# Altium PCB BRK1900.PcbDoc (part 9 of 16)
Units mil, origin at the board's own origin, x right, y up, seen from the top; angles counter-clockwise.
Board outline 8858.27 x 5905.51 mil, 10 copper layers (L1-TOP, L2-GND, L3-PWR, L4-GND, L5-PWR, L6-PWR, L7-GND, L8-SIG, L9-GND, L10-BOT), stack 48.824 mil thick; 456 components, 571 nets, 2296 pads, 2416 vias.
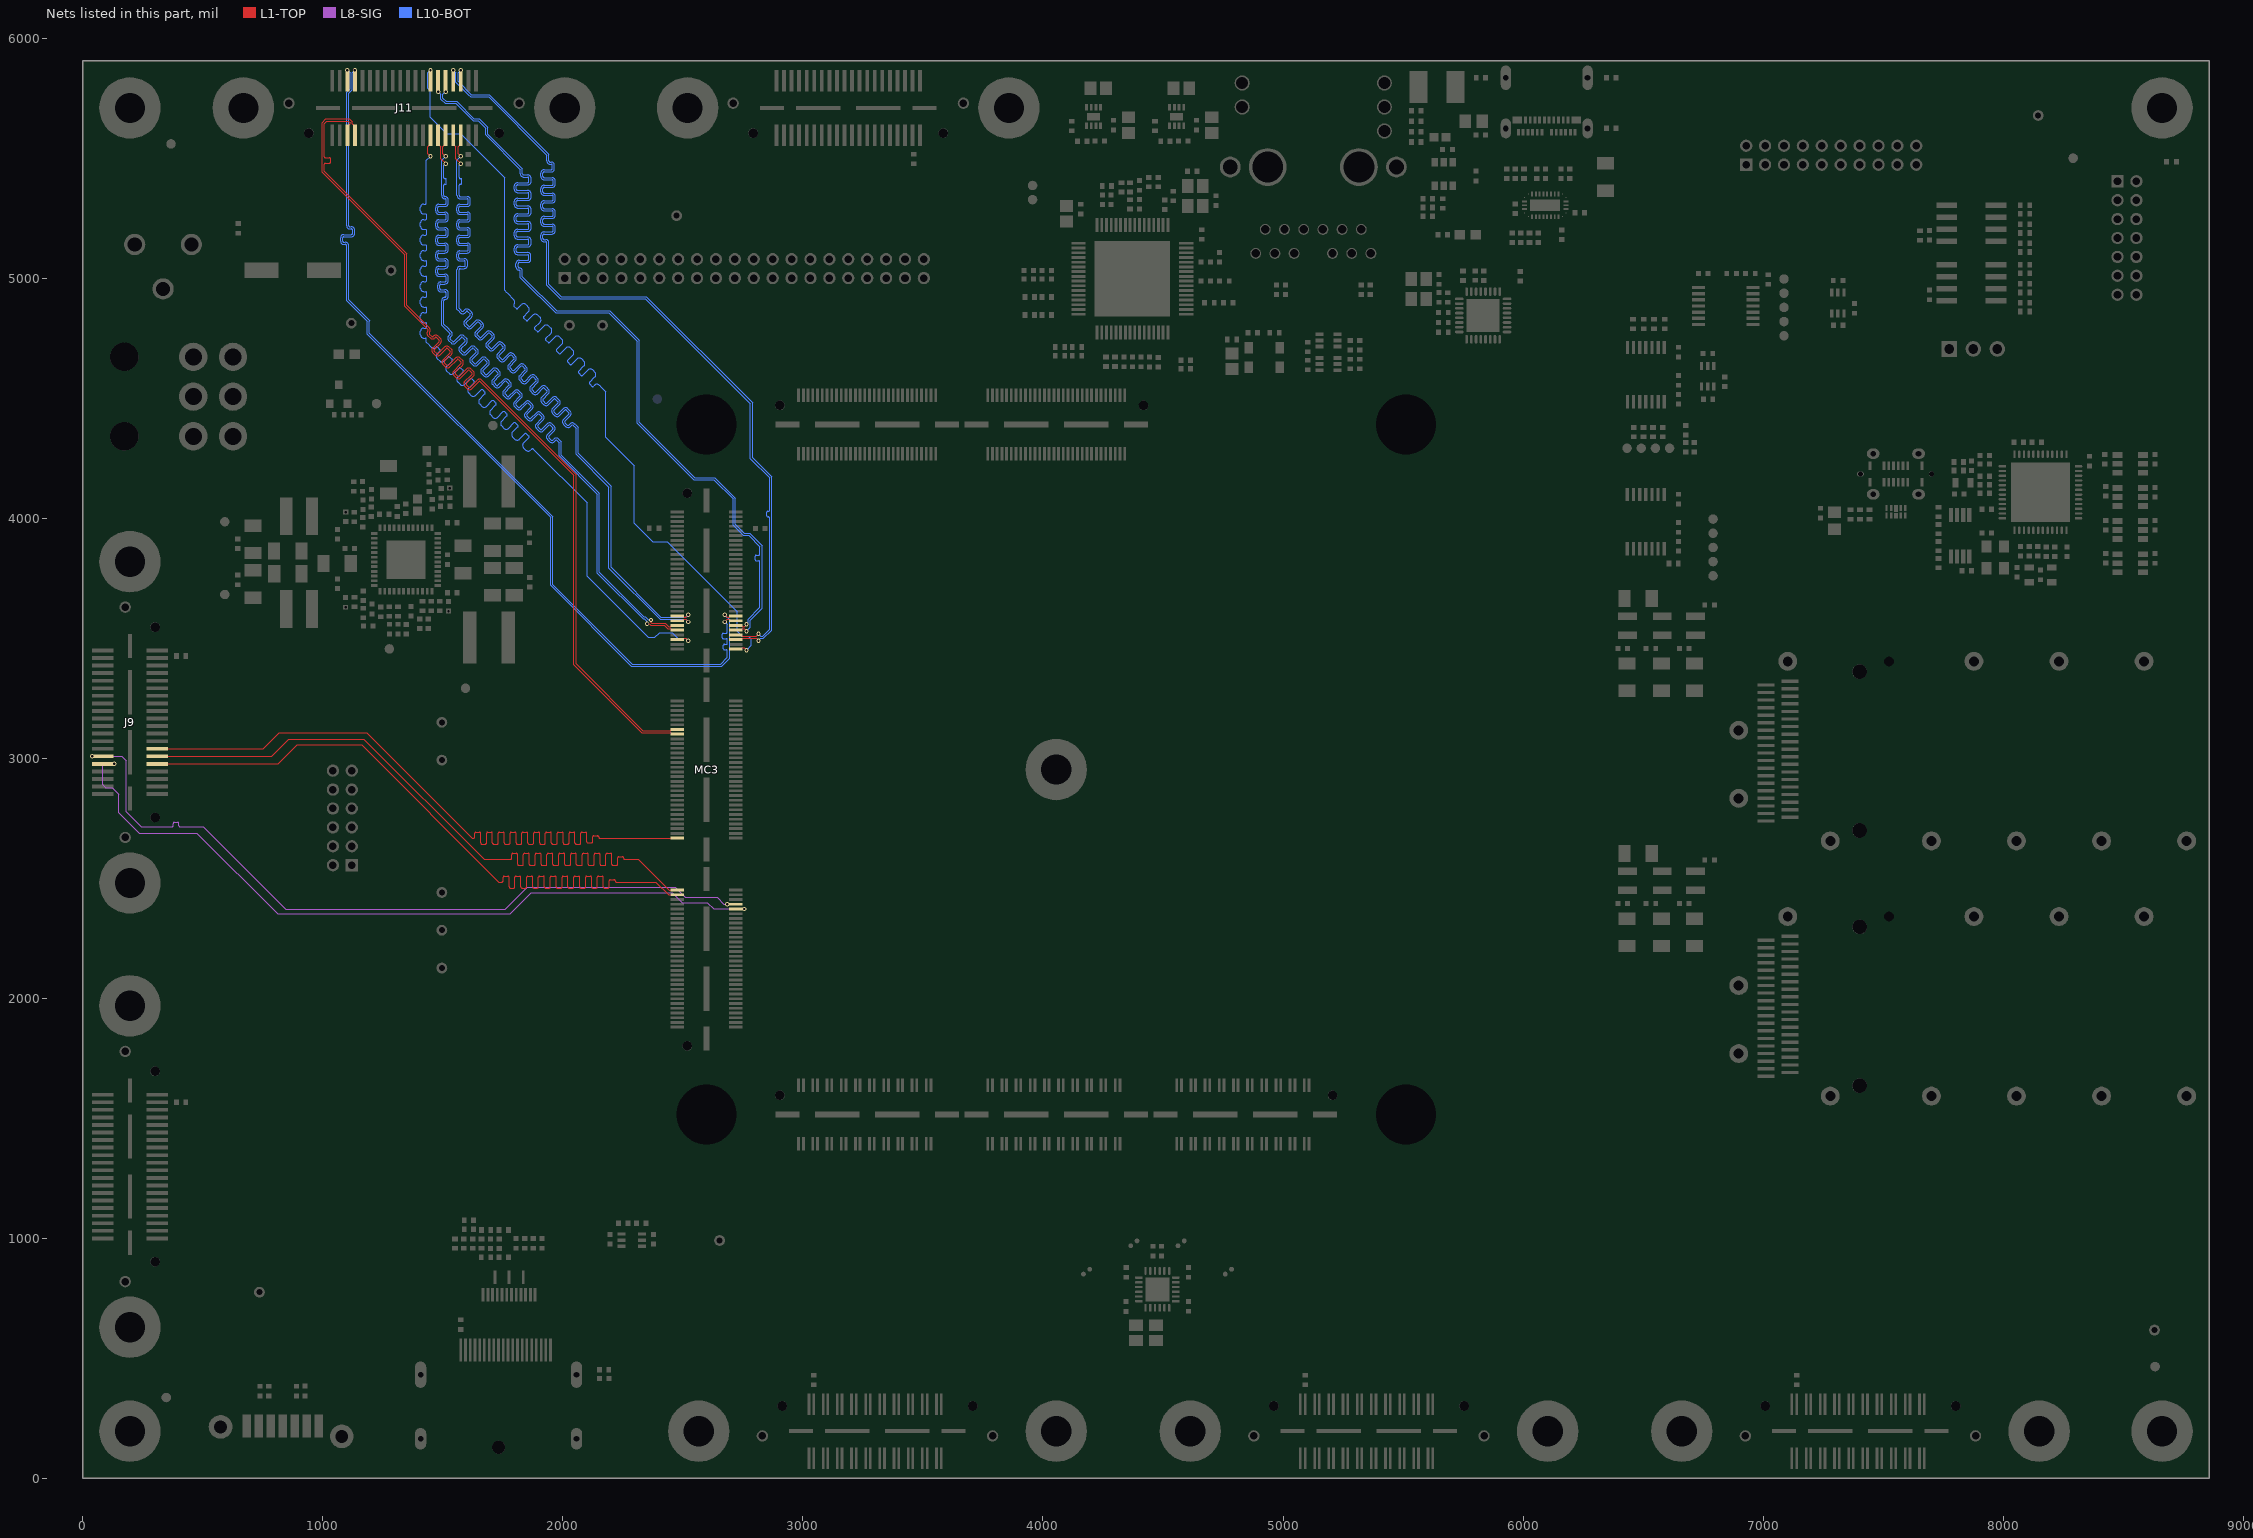
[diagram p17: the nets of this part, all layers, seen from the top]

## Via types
v1: diameter 18, hole 10, L1-TOP to L10-BOT, tented both sides, 2170 vias
v2: diameter 20, hole 10, L1-TOP to L10-BOT, tented both sides, 246 vias

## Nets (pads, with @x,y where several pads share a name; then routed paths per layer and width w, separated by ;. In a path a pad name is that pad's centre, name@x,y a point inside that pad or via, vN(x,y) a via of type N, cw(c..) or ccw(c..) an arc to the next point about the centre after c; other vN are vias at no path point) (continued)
SZG_PORTB_S23: J9.28 MC3.61 | length 3294.4
  L1-TOP w4.55: J9.28@309.65,3039.41 752,3039.41 819.39,3106.79 1182.82,3106.79 1622.28,2667.32 1625.98,2667.32 1628.26,2667.32 ccw(c1628.26,2672.23) 1633.17,2672.23 1633.17,2687.41 cw(c1638.08,2687.41) 1638.08,2692.32 1652.81,2692.32 cw(c1652.81,2687.41) 1657.72,2687.41 1657.72,2647.23 ccw(c1662.63,2647.23) 1662.63,2642.32 1677.36,2642.32 ccw(c1677.36,2647.23) 1682.27,2647.23 1682.27,2687.41 cw(c1687.18,2687.41) 1687.18,2692.32 1701.91,2692.32 cw(c1701.91,2687.41) 1706.82,2687.41 1706.82,2647.23 ccw(c1711.73,2647.23) 1711.73,2642.32 1726.46,2642.32 ccw(c1726.46,2647.23) 1731.37,2647.23 1731.37,2687.41 cw(c1736.28,2687.41) 1736.28,2692.32 1751.01,2692.32 cw(c1751.01,2687.41) 1755.92,2687.41 1755.92,2647.23 ccw(c1760.83,2647.23) 1760.83,2642.32 1775.56,2642.32 ccw(c1775.56,2647.23) 1780.47,2647.23 1780.47,2687.41 cw(c1785.38,2687.41) 1785.38,2692.32 1800.11,2692.32 cw(c1800.11,2687.41) 1805.02,2687.41 1805.02,2647.23 ccw(c1809.93,2647.23) 1809.93,2642.32 1824.66,2642.32 ccw(c1824.66,2647.23) 1829.57,2647.23 1829.57,2687.41 cw(c1834.48,2687.41) 1834.48,2692.32 1849.21,2692.32 cw(c1849.21,2687.41) 1854.12,2687.41 1854.12,2647.23 ccw(c1859.03,2647.23) 1859.03,2642.32 1873.76,2642.32 ccw(c1873.76,2647.23) 1878.67,2647.23 1878.67,2687.41 cw(c1883.58,2687.41) 1883.58,2692.32 1898.31,2692.32 cw(c1898.31,2687.41) 1903.22,2687.41 1903.22,2647.23 ccw(c1908.13,2647.23) 1908.13,2642.32 1922.86,2642.32 ccw(c1922.86,2647.23) 1927.77,2647.23 1927.77,2687.41 cw(c1932.68,2687.41) 1932.68,2692.32 1947.41,2692.32 cw(c1947.41,2687.41) 1952.32,2687.41 1952.32,2647.23 ccw(c1957.23,2647.23) 1957.23,2642.32 1971.96,2642.32 ccw(c1971.96,2647.23) 1976.87,2647.23 1976.87,2687.41 cw(c1981.78,2687.41) 1981.78,2692.32 1996.51,2692.32 cw(c1996.51,2687.41) 2001.42,2687.41 2001.42,2647.23 ccw(c2006.33,2647.23) 2006.33,2642.32 2021.06,2642.32 ccw(c2021.06,2647.23) 2025.97,2647.23 2025.97,2687.41 cw(c2030.88,2687.41) 2030.88,2692.32 2045.61,2692.32 cw(c2045.61,2687.41) 2050.52,2687.41 2050.52,2647.23 ccw(c2055.43,2647.23) 2055.43,2642.32 2070.16,2642.32 ccw(c2070.16,2647.23) 2075.07,2647.23 2075.07,2687.41 cw(c2079.98,2687.41) 2079.98,2692.32 2094.71,2692.32 cw(c2094.71,2687.41) 2099.62,2687.41 2099.62,2652.02 ccw(c2104.53,2652.02) 2104.53,2647.11 2119.26,2647.11 ccw(c2119.26,2652.02) 2124.17,2652.02 2124.17,2672.23 cw(c2129.08,2672.23) 2129.08,2677.14 2143.81,2677.14 cw(c2143.81,2672.23) 2148.72,2672.23 ccw(c2153.63,2672.23) 2153.63,2667.32 2228.35,2667.32 MC3.61@2476.77,2667.32
SZG_PORTB_S24: J9.29 MC3.54 | length 3133.3
  L8-SIG w4.05: v1@36.05,3007.91 162.86,3007.91 181.76,2989.01 181.76,2776.24 244,2714 370.08,2714 372.1,2714 ccw(c372.1,2718.81) 376.91,2718.81 376.91,2727.72 cw(c381.72,2727.72) 381.72,2732.54 396.15,2732.54 cw(c396.15,2727.72) 400.96,2727.72 400.96,2718.81 ccw(c405.77,2718.81) 405.77,2714 433.07,2714 503,2714 846.24,2370.76 1760.53,2370.76 1851.76,2462 2468,2462 2510,2420 2642.99,2420 2671.26,2391.73 v1(2685.08,2391.73)
  other v1: 39.35,3007.91
SZG_PORTB_S25: J9.30 MC3.59 | length 3294.4
  L1-TOP w4.55: J9.30@309.65,3007.91 787.43,3007.91 858.76,3079.23 1171.4,3079.23 1671.89,2578.74 1779.53,2578.74 1781.8,2578.74 ccw(c1781.8,2583.65) 1786.71,2583.65 1786.71,2598.83 cw(c1791.62,2598.83) 1791.62,2603.74 1806.35,2603.74 cw(c1806.35,2598.83) 1811.26,2598.83 1811.26,2558.65 ccw(c1816.17,2558.65) 1816.17,2553.74 1830.9,2553.74 ccw(c1830.9,2558.65) 1835.81,2558.65 1835.81,2598.83 cw(c1840.72,2598.83) 1840.72,2603.74 1855.45,2603.74 cw(c1855.45,2598.83) 1860.36,2598.83 1860.36,2558.65 ccw(c1865.27,2558.65) 1865.27,2553.74 1880,2553.74 ccw(c1880,2558.65) 1884.91,2558.65 1884.91,2598.83 cw(c1889.82,2598.83) 1889.82,2603.74 1904.55,2603.74 cw(c1904.55,2598.83) 1909.46,2598.83 1909.46,2558.65 ccw(c1914.37,2558.65) 1914.37,2553.74 1929.1,2553.74 ccw(c1929.1,2558.65) 1934.01,2558.65 1934.01,2598.83 cw(c1938.92,2598.83) 1938.92,2603.74 1953.65,2603.74 cw(c1953.65,2598.83) 1958.56,2598.83 1958.56,2558.65 ccw(c1963.47,2558.65) 1963.47,2553.74 1978.2,2553.74 ccw(c1978.2,2558.65) 1983.11,2558.65 1983.11,2598.83 cw(c1988.02,2598.83) 1988.02,2603.74 2002.75,2603.74 cw(c2002.75,2598.83) 2007.66,2598.83 2007.66,2558.65 ccw(c2012.57,2558.65) 2012.57,2553.74 2027.3,2553.74 ccw(c2027.3,2558.65) 2032.21,2558.65 2032.21,2598.83 cw(c2037.12,2598.83) 2037.12,2603.74 2051.85,2603.74 cw(c2051.85,2598.83) 2056.76,2598.83 2056.76,2558.65 ccw(c2061.67,2558.65) 2061.67,2553.74 2076.4,2553.74 ccw(c2076.4,2558.65) 2081.31,2558.65 2081.31,2598.83 cw(c2086.22,2598.83) 2086.22,2603.74 2100.95,2603.74 cw(c2100.95,2598.83) 2105.86,2598.83 2105.86,2558.65 ccw(c2110.77,2558.65) 2110.77,2553.74 2125.5,2553.74 ccw(c2125.5,2558.65) 2130.41,2558.65 2130.41,2598.83 cw(c2135.32,2598.83) 2135.32,2603.74 2150.05,2603.74 cw(c2150.05,2598.83) 2154.96,2598.83 2154.96,2558.65 ccw(c2159.87,2558.65) 2159.87,2553.74 2174.6,2553.74 ccw(c2174.6,2558.65) 2179.51,2558.65 2179.51,2598.83 cw(c2184.42,2598.83) 2184.42,2603.74 2199.15,2603.74 cw(c2199.15,2598.83) 2204.06,2598.83 2204.06,2558.65 ccw(c2208.97,2558.65) 2208.97,2553.74 2223.7,2553.74 ccw(c2223.7,2558.65) 2228.61,2558.65 2228.61,2584.69 cw(c2233.52,2584.69) 2233.52,2589.6 2248.25,2589.6 cw(c2248.25,2584.69) 2253.16,2584.69 2253.16,2583.65 ccw(c2258.07,2583.65) 2258.07,2578.74 2303.15,2578.74 2314.96,2578.74 2442.91,2450.79 MC3.59@2476.77,2450.79
SZG_PORTB_S26: J9.31 MC3.52 | length 3133.3
  L8-SIG w4.05: v1(132.05,2976.41) 92.16,2976.41 84.37,2968.62 84.37,2889.91 96.33,2877.95 122.05,2877.95 149.55,2850.45 149.55,2773.02 234.56,2688 476,2688 812.24,2351.76 1780.9,2351.76 1869.13,2440 2456,2440 2498,2398 2602,2398 2627.95,2372.05 v1(2755.08,2372.05)
SZG_PORTB_S27: J9.32 MC3.57 | length 3294.4
  L1-TOP w4.55: J9.32@309.65,2976.41 814.99,2976.41 893.7,3055.12 1161.42,3055.12 1732.28,2484.25 1744.09,2484.25 1746.37,2484.25 ccw(c1746.37,2489.16) 1751.28,2489.16 1751.28,2504.34 cw(c1756.19,2504.34) 1756.19,2509.25 1770.92,2509.25 cw(c1770.92,2504.34) 1775.83,2504.34 1775.83,2464.16 ccw(c1780.74,2464.16) 1780.74,2459.25 1795.47,2459.25 ccw(c1795.47,2464.16) 1800.38,2464.16 1800.38,2504.34 cw(c1805.29,2504.34) 1805.29,2509.25 1820.02,2509.25 cw(c1820.02,2504.34) 1824.93,2504.34 1824.93,2464.16 ccw(c1829.84,2464.16) 1829.84,2459.25 1844.57,2459.25 ccw(c1844.57,2464.16) 1849.48,2464.16 1849.48,2504.34 cw(c1854.39,2504.34) 1854.39,2509.25 1869.12,2509.25 cw(c1869.12,2504.34) 1874.03,2504.34 1874.03,2464.16 ccw(c1878.94,2464.16) 1878.94,2459.25 1893.67,2459.25 ccw(c1893.67,2464.16) 1898.58,2464.16 1898.58,2504.34 cw(c1903.49,2504.34) 1903.49,2509.25 1918.22,2509.25 cw(c1918.22,2504.34) 1923.13,2504.34 1923.13,2464.16 ccw(c1928.04,2464.16) 1928.04,2459.25 1942.77,2459.25 ccw(c1942.77,2464.16) 1947.68,2464.16 1947.68,2504.34 cw(c1952.59,2504.34) 1952.59,2509.25 1967.32,2509.25 cw(c1967.32,2504.34) 1972.23,2504.34 1972.23,2464.16 ccw(c1977.14,2464.16) 1977.14,2459.25 1991.87,2459.25 ccw(c1991.87,2464.16) 1996.78,2464.16 1996.78,2504.34 cw(c2001.69,2504.34) 2001.69,2509.25 2016.42,2509.25 cw(c2016.42,2504.34) 2021.33,2504.34 2021.33,2464.16 ccw(c2026.24,2464.16) 2026.24,2459.25 2040.97,2459.25 ccw(c2040.97,2464.16) 2045.88,2464.16 2045.88,2504.34 cw(c2050.79,2504.34) 2050.79,2509.25 2065.52,2509.25 cw(c2065.52,2504.34) 2070.43,2504.34 2070.43,2464.16 ccw(c2075.34,2464.16) 2075.34,2459.25 2090.07,2459.25 ccw(c2090.07,2464.16) 2094.98,2464.16 2094.98,2504.34 cw(c2099.89,2504.34) 2099.89,2509.25 2114.62,2509.25 cw(c2114.62,2504.34) 2119.53,2504.34 2119.53,2464.16 ccw(c2124.44,2464.16) 2124.44,2459.25 2139.17,2459.25 ccw(c2139.17,2464.16) 2144.08,2464.16 2144.08,2504.34 cw(c2148.99,2504.34) 2148.99,2509.25 2163.72,2509.25 cw(c2163.72,2504.34) 2168.63,2504.34 2168.63,2464.16 ccw(c2173.54,2464.16) 2173.54,2459.25 2188.27,2459.25 ccw(c2188.27,2464.16) 2193.18,2464.16 2193.18,2489.59 cw(c2198.09,2489.59) 2198.09,2494.5 2212.82,2494.5 cw(c2212.82,2489.59) 2217.73,2489.59 2217.73,2489.16 ccw(c2222.64,2489.16) 2222.64,2484.25 2299.21,2484.25 2387.75,2484.25 2440.9,2431.1 MC3.57@2476.77,2431.1
SZG_PORTC_C2P_CLKN: J11.36 MC3.107 | length 3871
  L1-TOP w3.3: J11.36@1102.38,5595.86 1102.38,5632.38 1113.63,5643.63 1113.63,5646.73 1106.51,5653.85 1016.85,5653.85 1006,5643 1006,5554.73 1006,5506.35 ccw(c1010.66,5506.35) 1010.66,5501.69 1027.71,5501.69 cw(c1027.71,5497.03) 1032.37,5497.03 1032.37,5483.05 cw(c1027.71,5483.05) 1027.71,5478.39 1010.66,5478.39 ccw(c1010.66,5473.73) 1006,5473.73 1006,5448.78 1006,5444.73 1350,5100.73 1350,4886.81 1417.81,4819.01 1420.84,4815.98 1443.98,4792.83 cw(c1434.33,4783.17) 1443.98,4773.51 ccw(c1447.28,4770.22) 1443.98,4766.92 1453.87,4757.04 ccw(c1457.16,4760.33) 1460.46,4757.04 1462.84,4759.41 1463.05,4759.41 cw(c1471.18,4748.44) 1480.84,4758.09 1490.72,4748.21 cw(c1481.06,4738.55) 1490.7,4728.87 1464.22,4702.39 ccw(c1467.51,4699.09) 1464.22,4695.8 1474.1,4685.91 ccw(c1477.4,4689.2) 1480.69,4685.91 1508.52,4713.73 1508.73,4713.73 cw(c1516.86,4702.76) 1526.52,4712.42 1536.4,4702.53 cw(c1526.74,4692.87) 1536.43,4683.25 1506.72,4653.53 ; 1506.7,4653.51 ccw(c1509.99,4650.21) 1506.7,4646.92 1516.58,4637.03 ccw(c1519.88,4640.33) 1523.17,4637.03 1554.19,4668.05 1554.41,4668.05 cw(c1562.54,4657.08) 1572.19,4666.74 1582.08,4656.85 cw(c1572.42,4647.19) 1582.11,4637.57 1552.4,4607.85 ; 1552.38,4607.83 ccw(c1555.67,4604.53) 1552.38,4601.24 1562.26,4591.35 ccw(c1565.56,4594.65) 1568.85,4591.35 1599.87,4622.38 1600.08,4622.38 cw(c1608.21,4611.4) 1617.87,4621.06 1627.76,4611.17 cw(c1618.1,4601.51) 1627.79,4591.89 1598.08,4562.17 ; 1598.05,4562.15 ccw(c1601.35,4558.86) 1598.05,4555.56 1607.94,4545.67 ccw(c1611.24,4548.97) 1614.53,4545.68 1643.18,4574.32 cw(c1652.83,4564.66) 1660.96,4575.64 1661.18,4575.64 1662.48,4574.33 1663.81,4573 1666.84,4569.97 2055,4181.81 2055,3393 2333.26,3114.74 2448.6,3114.74 2453.95,3120.08 MC3.107@2476.77,3120.08
SZG_PORTC_C2P_CLKP: J11.34 MC3.105 | length 3870.8
  L1-TOP w3.3: J11.34@1133.88,5595.86 1133.88,5632.65 1122.63,5643.9 1122.63,5650.45 1110.24,5662.85 1013.12,5662.85 997,5646.73 997,5441 1341,5097 1341,4883.09 1411.44,4812.64 1414.47,4809.61 1437.62,4786.47 cw(c1434.33,4783.17) 1437.62,4779.88 ccw(c1447.28,4770.22) 1437.65,4760.53 1447.48,4750.7 ; 1447.48,4750.7 ccw(c1457.16,4760.33) 1466.82,4750.67 1467.86,4751.71 ; 1467.88,4751.73 cw(c1471.18,4748.44) 1474.47,4751.73 1484.36,4741.85 cw(c1481.06,4738.55) 1484.36,4735.26 1457.85,4708.75 ccw(c1467.51,4699.09) 1457.88,4689.41 1467.71,4679.57 ccw(c1477.4,4689.2) 1487.06,4679.55 1513.54,4706.03 cw(c1516.86,4702.76) 1520.15,4706.05 1530.04,4696.17 cw(c1526.74,4692.87) 1530.04,4689.58 1499.01,4658.55 1499.01,4658.34 ccw(c1509.99,4650.21) 1500.36,4640.53 1510.19,4630.7 ccw(c1519.88,4640.33) 1529.54,4630.67 1559.22,4660.35 ; 1555.87,4585.02 ccw(c1565.56,4594.65) 1575.22,4584.99 1604.9,4614.67 cw(c1608.21,4611.4) 1611.51,4614.69 1621.39,4604.81 cw(c1618.1,4601.51) 1621.39,4598.22 1590.37,4567.2 1590.37,4566.99 ccw(c1601.35,4558.86) 1591.72,4549.17 1601.55,4539.34 ccw(c1611.24,4548.97) 1620.89,4539.31 1649.54,4567.96 cw(c1652.83,4564.66) 1656.15,4567.94 1657.45,4566.64 1660.48,4563.61 2046,4178.09 2046,3389.27 2329.54,3105.74 2448.92,3105.74 2454.26,3100.39 MC3.105@2476.77,3100.39 ; 1555.87,4585.02 1546.04,4594.85 cw(c1555.67,4604.53) 1544.69,4612.66 1544.69,4612.88 1575.72,4643.9 ccw(c1572.42,4647.19) 1575.72,4650.49 1565.83,4660.37 ccw(c1562.54,4657.08) 1559.24,4660.37
SZG_PORTC_P2C_CLKN: J11.35 MC3.136 | length 3724
  L1-TOP w3.3: v1@2675.08,3596.46 2676.08,3596.46 2685.36,3587.18 2692.1,3587.18 2697.44,3592.52 MC3.136@2720.08,3592.52
  L10-BOT w3.3: v1@1103.37,5866.17 1113.63,5855.9 1113.63,5789 1099,5774.37 1099,5297.6 1099,5218.49 ccw(c1112.66,5218.49) 1112.66,5204.83 1119.34,5204.83 cw(c1119.34,5200.17) 1124,5200.17 1124,5186.19 cw(c1119.34,5186.19) 1119.34,5181.53 1087.66,5181.53 ccw(c1087.66,5167.87) 1074,5167.87 1074,5153.89 ccw(c1087.66,5153.89) 1087.66,5140.23 1094.34,5140.23 cw(c1094.34,5135.57) 1099,5135.57 1099,5129.42 1099,4906.27 1185,4820.27 1185,4766.84 1948.82,4003.02 1948.82,3719.56 2285.37,3383 2661.73,3383 2694.78,3416.05 2694.78,3576.76 v1@2675.08,3596.46
  other v1: 2675.08,3597.46 1102.37,5866.17
SZG_PORTC_P2C_CLKP: J11.33 MC3.134 | length 3722.9
  L1-TOP w3.3: v1@2675.08,3568.9 2676.18,3568.9 2685.46,3578.18 2692.1,3578.18 2697.44,3572.83 MC3.134@2720.08,3572.83
  L10-BOT w3.3: v1@1132.89,5866.17 1122.63,5855.9 1122.63,5785.27 1108,5770.64 1108,5297.6 1108,5218.49 ccw(c1112.66,5218.49) 1112.66,5213.83 1119.34,5213.83 cw(c1119.34,5200.17) 1133,5200.17 1133,5186.19 cw(c1119.34,5186.19) 1119.34,5172.53 1087.66,5172.53 ccw(c1087.66,5167.87) 1083,5167.87 1083,5153.89 ccw(c1087.66,5153.89) 1087.66,5149.23 1094.34,5149.23 cw(c1094.34,5135.57) 1108,5135.57 1108,5129.42 1108,4910 1195.5,4822.5 ; 1194,4821 1194,4770.57 1957.82,4006.75 1957.82,3723.28 2289.1,3392 2658,3392 2685.78,3419.78 2685.78,3426.42 2685.78,3446.83 ccw(c2681.12,3446.83) 2681.12,3451.49 2673.71,3451.49 cw(c2673.71,3456.15) 2669.05,3456.15 2669.05,3470.13 cw(c2673.71,3470.13) 2673.71,3474.79 2681.12,3474.79 ccw(c2681.12,3479.45) 2685.78,3479.45 2685.78,3493.43 ccw(c2681.12,3493.43) 2681.12,3498.09 2668.76,3498.09 cw(c2668.76,3502.75) 2664.1,3502.75 2664.1,3516.73 cw(c2668.76,3516.73) 2668.76,3521.39 2681.12,3521.39 ccw(c2681.12,3526.05) 2685.78,3526.05 2685.78,3551 2685.78,3558.2 v1@2675.08,3568.9
  other v1: 2675.08,3567.8 1133.89,5866.17
SZG_PORTC_S0_D0P: J11.5 MC3.126 | length 3724.1
  L1-TOP w3.3: MC3.126@2720.08,3494.09 2742.67,3494.09 2748.01,3499.44 2805.8,3499.44 v1@2815.08,3490.16
  L10-BOT w3.3: v1@1573.89,5866.17 1563.63,5855.9 1563.63,5819.37 1619.11,5763.89 1694.11,5763.89 1939.43,5518.57 1942.07,5515.93 1942.07,5504.67 1942.07,5487.97 ccw(c1946.73,5487.97) 1946.73,5483.31 1951.3,5483.31 cw(c1951.3,5469.65) 1964.96,5469.65 1964.96,5455.67 cw(c1951.3,5455.67) 1951.3,5442.01 1921.73,5442.01 ccw(c1921.73,5437.35) 1917.07,5437.35 1917.07,5423.37 ccw(c1921.73,5423.37) 1921.73,5418.71 1954.89,5418.71 cw(c1954.89,5405.05) 1968.55,5405.05 1968.55,5391.07 cw(c1954.89,5391.07) 1954.89,5377.41 1921.73,5377.41 ccw(c1921.73,5372.75) 1917.07,5372.75 1917.07,5358.77 ccw(c1921.73,5358.77) 1921.73,5354.11 1954.89,5354.11 cw(c1954.89,5340.45) 1968.55,5340.45 1968.55,5326.47 cw(c1954.89,5326.47) 1954.89,5312.81 1921.73,5312.81 ccw(c1921.73,5308.15) 1917.07,5308.15 1917.07,5294.17 ccw(c1921.73,5294.17) 1921.73,5289.51 1954.89,5289.51 cw(c1954.89,5275.85) 1968.55,5275.85 1968.55,5261.87 cw(c1954.89,5261.87) 1954.89,5248.21 1921.73,5248.21 ccw(c1921.73,5243.55) 1917.07,5243.55 1917.07,5229.57 ccw(c1921.73,5229.57) 1921.73,5224.91 1954.89,5224.91 cw(c1954.89,5211.25) 1968.55,5211.25 1968.55,5197.27 cw(c1954.89,5197.27) 1954.89,5183.61 1921.73,5183.61 ccw(c1921.73,5178.95) 1917.07,5178.95 1917.07,5164.97 ccw(c1921.73,5164.97) 1921.73,5160.31 1928.41,5160.31 cw(c1928.41,5146.65) 1942.07,5146.65 1942.07,5140.5 1942.07,4973.93 1993,4923 2346.73,4923 2790.04,4479.69 2790.04,4251.8 2870,4171.84 2870,4058.09 2870,3533.71 2835.73,3499.44 2824.36,3499.44 v1@2815.08,3490.16
  other v1: 2815.08,3489.06 1574.89,5866.17
SZG_PORTC_S1_D1P: J11.6 MC3.133 | length 3773.8
  L1-TOP w3.3: v1(1574.88,5507.28) 1563.63,5518.53 1563.63,5547.62 1574.88,5558.87 J11.6@1574.88,5595.86 ; MC3.133@2476.77,3572.83 2499.41,3572.83 2504.7,3578.13 2512.7,3578.13 2521.77,3569.06 v1@2521.77,3568.9
  L10-BOT w3.3: v1(1574.88,5507.28) 1559,5491.4 1559,5350.39 1559,5344.24 ccw(c1572.66,5344.24) 1572.66,5330.58 1601.49,5330.58 cw(c1601.49,5325.92) 1606.15,5325.92 1606.15,5311.94 cw(c1601.49,5311.94) 1601.49,5307.28 1570.94,5307.28 ccw(c1570.94,5293.62) 1557.28,5293.62 1557.28,5279.64 ccw(c1570.94,5279.64) 1570.94,5265.98 1601.49,5265.98 cw(c1601.49,5261.32) 1606.15,5261.32 1606.15,5247.34 cw(c1601.49,5247.34) 1601.49,5242.68 1570.94,5242.68 ccw(c1570.94,5229.02) 1557.28,5229.02 1557.28,5215.04 ccw(c1570.94,5215.04) 1570.94,5201.38 1601.49,5201.38 cw(c1601.49,5196.72) 1606.15,5196.72 1606.15,5182.74 cw(c1601.49,5182.74) 1601.49,5178.08 1570.94,5178.08 ccw(c1570.94,5164.42) 1557.28,5164.42 1557.28,5150.44 ccw(c1570.94,5150.44) 1570.94,5136.78 1601.49,5136.78 cw(c1601.49,5132.12) 1606.15,5132.12 1606.15,5118.14 cw(c1601.49,5118.14) 1601.49,5113.48 1570.94,5113.48 ccw(c1570.94,5099.82) 1557.28,5099.82 1557.28,5085.84 ccw(c1570.94,5085.84) 1570.94,5072.18 1589.47,5072.18 cw(c1589.47,5067.52) 1594.13,5067.52 1594.13,5053.54 cw(c1589.47,5053.54) 1589.47,5048.88 1572.66,5048.88 ccw(c1572.66,5035.22) 1559,5035.22 1559,4958.09 1559,4870.13 1560.42,4868.72 1563.45,4865.69 1573.15,4855.98 ccw(c1582.81,4865.64) 1592.47,4855.98 1597.17,4860.68 ; 1597.19,4860.71 cw(c1600.49,4857.41) 1603.78,4860.71 1613.67,4850.82 cw(c1610.37,4847.53) 1613.67,4844.23 1589.95,4820.51 1589.95,4820.3 ccw(c1600.93,4812.17) 1591.29,4802.49 1601.12,4792.65 ccw(c1610.81,4802.28) 1620.47,4792.63 1642.85,4815 ; 1642.87,4815.03 cw(c1646.17,4811.73) 1649.46,4815.03 1659.35,4805.14 cw(c1656.05,4801.85) 1659.35,4798.55 1635.63,4774.83 1635.63,4774.62 ccw(c1646.61,4766.49) 1636.97,4756.81 1646.8,4746.98 ccw(c1656.49,4756.61) 1666.15,4746.95 1688.53,4769.33 cw(c1691.85,4766.05) 1695.14,4769.35 1705.03,4759.46 cw(c1701.73,4756.17) 1705.03,4752.87 1681.31,4729.15 1681.31,4728.94 ccw(c1692.28,4720.81) 1682.65,4711.13 1692.48,4701.3 ccw(c1702.17,4710.93) 1711.83,4701.27 1734.21,4723.65 ; 1734.23,4723.67 cw(c1737.53,4720.37) 1740.82,4723.67 1750.71,4713.78 cw(c1747.41,4710.49) 1750.71,4707.19 1726.99,4683.47 1726.99,4683.26 ccw(c1737.96,4675.13) 1728.33,4665.45 1738.16,4655.62 ; 1738.16,4655.62 ccw(c1747.85,4665.25) 1757.51,4655.59 1779.89,4677.97 cw(c1783.2,4674.7) 1786.5,4677.99 1796.38,4668.1 cw(c1793.09,4664.81) 1796.38,4661.51 1772.67,4637.8 1772.67,4637.58 ccw(c1783.64,4629.45) 1774.01,4619.77 ; 1774.01,4619.77 1783.84,4609.94 ccw(c1793.53,4619.57) 1803.19,4609.91 1825.57,4632.29 ; 1825.59,4632.31 cw(c1828.88,4629.02) 1832.18,4632.31 1842.06,4622.43 cw(c1838.77,4619.13) 1842.06,4615.84 1818.34,4592.12 1818.34,4591.91 ccw(c1829.32,4583.78) 1819.69,4574.09 1829.52,4564.26 ccw(c1839.21,4573.89) 1848.87,4564.23 1871.24,4586.61 ; 1871.27,4586.63 cw(c1874.56,4583.34) 1877.86,4586.63 1887.74,4576.75 cw(c1884.45,4573.45) 1887.74,4570.16 1864.02,4546.44 1864.02,4546.23 ccw(c1875,4538.1) 1865.37,4528.41 1875.2,4518.58 ccw(c1884.89,4528.21) 1894.54,4518.55 1916.92,4540.93 ; 1916.95,4540.95 cw(c1920.24,4537.66) 1923.54,4540.95 1933.42,4531.07 cw(c1930.13,4527.77) 1933.42,4524.48 1909.7,4500.76 1909.7,4500.55 ccw(c1920.68,4492.42) 1911.05,4482.73 1920.88,4472.9 ccw(c1930.56,4482.53) 1940.22,4472.87 1962.6,4495.25 ; 1956.73,4437.05 cw(c1966.36,4446.74) 1955.38,4454.87 1955.38,4455.08 1979.1,4478.8 ccw(c1975.81,4482.09) 1979.1,4485.39 1969.21,4495.27 ccw(c1965.92,4491.98) 1962.62,4495.27 ; 1956.73,4437.05 1966.56,4427.22 ccw(c1976.24,4436.85) 1985.9,4427.19 2008.28,4449.57 cw(c2011.6,4446.3) 2014.89,4449.6 2024.78,4439.71 cw(c2021.48,4436.41) 2024.78,4433.12 2001.06,4409.4 2001.06,4409.19 ccw(c2012.04,4401.06) 2002.4,4391.37 2012.23,4381.54 ccw(c2021.92,4391.17) 2031.58,4381.51 2036.31,4386.24 cw(c2039.6,4382.94) 2042.91,4386.22 ; 2042.92,4386.21 2044.21,4384.92 2047.24,4381.89 2055.12,4374.02 2055.12,4266.35 2192,4129.47 2192,3791.16 2404.98,3578.18 2512.49,3578.18 v1@2521.77,3568.9
  other v1: 2521.77,3567.8
SZG_PORTC_S2_D0N: J11.7 MC3.128 | length 3724.3
  L1-TOP w3.3: MC3.128@2720.08,3513.78 2742.76,3513.78 2748.1,3508.44 2805.8,3508.44 v1@2815.08,3517.72
  L10-BOT w3.3: v1@1544.37,5866.17 1554.63,5855.9 1554.63,5815.64 1603.64,5766.64 1615.38,5754.89 1690.38,5754.89 1933.07,5512.2 1933.07,5504.67 1933.07,5487.97 ccw(c1946.73,5487.97) 1946.73,5474.31 1951.3,5474.31 cw(c1951.3,5469.65) 1955.96,5469.65 1955.96,5455.67 cw(c1951.3,5455.67) 1951.3,5451.01 1921.73,5451.01 ccw(c1921.73,5437.35) 1908.07,5437.35 1908.07,5423.37 ccw(c1921.73,5423.37) 1921.73,5409.71 1954.89,5409.71 cw(c1954.89,5405.05) 1959.55,5405.05 1959.55,5391.07 cw(c1954.89,5391.07) 1954.89,5386.41 1921.73,5386.41 ccw(c1921.73,5372.75) 1908.07,5372.75 1908.07,5358.77 ccw(c1921.73,5358.77) 1921.73,5345.11 1954.89,5345.11 cw(c1954.89,5340.45) 1959.55,5340.45 1959.55,5326.47 cw(c1954.89,5326.47) 1954.89,5321.81 1921.73,5321.81 ccw(c1921.73,5308.15) 1908.07,5308.15 1908.07,5294.17 ccw(c1921.73,5294.17) 1921.73,5280.51 1954.89,5280.51 cw(c1954.89,5275.85) 1959.55,5275.85 1959.55,5261.87 cw(c1954.89,5261.87) 1954.89,5257.21 1921.73,5257.21 ccw(c1921.73,5243.55) 1908.07,5243.55 1908.07,5229.57 ccw(c1921.73,5229.57) 1921.73,5215.91 1954.89,5215.91 cw(c1954.89,5211.25) 1959.55,5211.25 1959.55,5197.27 cw(c1954.89,5197.27) 1954.89,5192.61 1921.73,5192.61 ccw(c1921.73,5178.95) 1908.07,5178.95 1908.07,5164.97 ccw(c1921.73,5164.97) 1921.73,5151.31 1928.41,5151.31 cw(c1928.41,5146.65) 1933.07,5146.65 1933.07,5140.5 1933.07,4970.2 1989.27,4914 2343,4914 2781.04,4475.96 2781.04,4248.07 2861,4168.11 2861,4058.09 2861,4033.14 cw(c2856.34,4033.14) 2856.34,4028.48 2854.1,4028.48 ccw(c2854.1,4023.82) 2849.44,4023.82 2849.44,4009.84 ccw(c2854.1,4009.84) 2854.1,4005.18 2856.34,4005.18 cw(c2856.34,4000.52) 2861,4000.52 2861,3984.25 2861,3537.44 2832,3508.44 2824.36,3508.44 v1@2815.08,3517.72
  other v1: 2815.08,3518.72 1543.37,5866.17
SZG_PORTC_S3_D1N: J11.8 MC3.135 | length 3773.8
  L1-TOP w3.3: J11.8@1543.38,5595.86 1543.38,5559 1554.63,5547.75 1554.63,5498 v1@1574.88,5477.75 ; MC3.135@2476.77,3592.52 2499.41,3592.52 2504.8,3587.13 2512.7,3587.13 2521.77,3596.2 v1@2521.77,3596.46
  L10-BOT w3.3: v1@1574.88,5477.75 1568,5470.87 1568,5437.01 1568,5419.09 ccw(c1572.66,5419.09) 1572.66,5414.43 1574.69,5414.43 cw(c1574.69,5409.77) 1579.35,5409.77 1579.35,5395.79 cw(c1574.69,5395.79) 1574.69,5391.13 1572.66,5391.13 ccw(c1572.66,5386.47) 1568,5386.47 1568,5361.52 1568,5350.39 1568,5344.24 ccw(c1572.66,5344.24) 1572.66,5339.58 1601.49,5339.58 cw(c1601.49,5325.92) 1615.15,5325.92 1615.15,5311.94 cw(c1601.49,5311.94) 1601.49,5298.28 1570.94,5298.28 ccw(c1570.94,5293.62) 1566.28,5293.62 1566.28,5279.64 ccw(c1570.94,5279.64) 1570.94,5274.98 1601.49,5274.98 cw(c1601.49,5261.32) 1615.15,5261.32 1615.15,5247.34 cw(c1601.49,5247.34) 1601.49,5233.68 1570.94,5233.68 ccw(c1570.94,5229.02) 1566.28,5229.02 1566.28,5215.04 ccw(c1570.94,5215.04) 1570.94,5210.38 1601.49,5210.38 cw(c1601.49,5196.72) 1615.15,5196.72 1615.15,5182.74 cw(c1601.49,5182.74) 1601.49,5169.08 1570.94,5169.08 ccw(c1570.94,5164.42) 1566.28,5164.42 1566.28,5150.44 ccw(c1570.94,5150.44) 1570.94,5145.78 1601.49,5145.78 cw(c1601.49,5132.12) 1615.15,5132.12 1615.15,5118.14 cw(c1601.49,5118.14) 1601.49,5104.48 1570.94,5104.48 ccw(c1570.94,5099.82) 1566.28,5099.82 1566.28,5085.84 ccw(c1570.94,5085.84) 1570.94,5081.18 1589.47,5081.18 cw(c1589.47,5067.52) 1603.13,5067.52 1603.13,5053.54 cw(c1589.47,5053.54) 1589.47,5039.88 1572.66,5039.88 ccw(c1572.66,5035.22) 1568,5035.22 1568,4958.09 1568,4876.3 1568,4873.86 1569.81,4872.05 1579.52,4862.35 ccw(c1582.81,4865.64) 1586.11,4862.35 1592.15,4868.39 1592.36,4868.39 cw(c1600.49,4857.41) 1610.15,4867.07 1620.03,4857.18 cw(c1610.37,4847.53) 1620.07,4837.9 1597.65,4815.49 ; 1597.63,4815.47 ccw(c1600.93,4812.17) 1597.63,4808.88 1607.52,4798.99 ccw(c1610.81,4802.28) 1614.11,4798.99 1637.83,4822.71 1638.04,4822.71 cw(c1646.17,4811.73) 1655.83,4821.39 1665.71,4811.51 cw(c1656.05,4801.85) 1665.74,4792.22 1643.33,4769.81 ; 1643.31,4769.79 ccw(c1646.61,4766.49) 1643.31,4763.2 1653.2,4753.31 ccw(c1656.49,4756.61) 1659.79,4753.31 1683.51,4777.03 1683.72,4777.03 cw(c1691.85,4766.05) 1701.51,4775.71 1711.39,4765.83 cw(c1701.73,4756.17) 1711.42,4746.54 1689.01,4724.13 ; 1688.99,4724.11 ccw(c1692.28,4720.81) 1688.99,4717.52 1698.87,4707.63 ccw(c1702.17,4710.93) 1705.46,4707.63 1729.18,4731.35 1729.4,4731.35 cw(c1737.53,4720.37) 1747.18,4730.03 1757.07,4720.15 cw(c1747.41,4710.49) 1757.1,4700.86 1734.69,4678.45 ; 1734.67,4678.43 ccw(c1737.96,4675.13) 1734.67,4671.84 1744.55,4661.95 ccw(c1747.85,4665.25) 1751.14,4661.95 1774.86,4685.67 1775.07,4685.67 cw(c1783.2,4674.7) 1792.86,4684.35 1802.75,4674.47 cw(c1793.09,4664.81) 1802.78,4655.18 1780.37,4632.77 ; 1780.35,4632.75 ccw(c1783.64,4629.45) 1780.35,4626.16 1790.23,4616.27 ccw(c1793.53,4619.57) 1796.82,4616.27 1820.54,4639.99 1820.75,4639.99 cw(c1828.88,4629.02) 1838.54,4638.68 1848.43,4628.79 cw(c1838.77,4619.13) 1848.46,4609.51 1826.05,4587.09 ; 1826.03,4587.07 ccw(c1829.32,4583.78) 1826.03,4580.48 1835.91,4570.59 ccw(c1839.21,4573.89) 1842.5,4570.59 1866.22,4594.31 1866.43,4594.31 cw(c1874.56,4583.34) 1884.22,4593 1894.11,4583.11 cw(c1884.45,4573.45) 1894.14,4563.83 1871.73,4541.41 ; 1871.71,4541.39 ccw(c1875,4538.1) 1871.71,4534.8 1881.59,4524.92 ccw(c1884.89,4528.21) 1888.18,4524.92 1911.9,4548.64 1912.11,4548.64 cw(c1920.24,4537.66) 1929.9,4547.32 1939.79,4537.43 cw(c1930.13,4527.77) 1939.82,4518.15 1917.41,4495.74 ; 1917.38,4495.71 ccw(c1920.68,4492.42) 1917.38,4489.12 1927.27,4479.24 ccw(c1930.56,4482.53) 1933.86,4479.24 1957.58,4502.96 1957.79,4502.96 cw(c1965.92,4491.98) 1975.58,4501.64 1985.46,4491.75 cw(c1975.81,4482.09) 1985.5,4472.47 1963.09,4450.06 ; 1963.06,4450.03 ccw(c1966.36,4446.74) 1963.06,4443.44 1972.95,4433.56 ccw(c1976.24,4436.85) 1979.54,4433.56 2003.26,4457.28 2003.47,4457.28 cw(c2011.6,4446.3) 2021.26,4455.96 2031.14,4446.07 cw(c2021.48,4436.41) 2031.18,4426.79 2008.76,4404.38 ; 2008.74,4404.35 ccw(c2012.04,4401.06) 2008.74,4397.76 2018.63,4387.88 ccw(c2021.92,4391.17) 2025.22,4387.88 2029.94,4392.6 cw(c2039.6,4382.94) 2047.73,4393.92 2047.94,4393.92 2049.25,4392.61 2050.58,4391.28 2053.61,4388.25 2064.12,4377.74 2064.12,4270.08 2201,4133.2 2201,3794.88 2408.71,3587.18 2512.49,3587.18 v1@2521.77,3596.46
  other v1: 2521.77,3597.46 1574.88,5476.75
SZG_PORTC_S4_D2P: J11.9 MC3.130 | length 3724.1
  L1-TOP w3.3: MC3.130@2720.08,3533.46 2742.72,3533.46 2748.01,3538.76 2756.01,3538.76 2765.08,3529.69 v1@2765.08,3529.53
  L10-BOT w3.3: v1@1510.89,5776.76 1500.63,5766.5 1500.63,5749.37 1513.48,5736.52 1557.21,5736.52 1559.85,5733.88 1629.73,5664 1651.73,5664 1687,5628.73 1687,5600 1831.83,5455.17 1831.83,5440.46 1831.83,5434.31 ccw(c1836.49,5434.31) 1836.49,5429.65 1854.05,5429.65 cw(c1854.05,5415.99) 1867.71,5415.99 1867.71,5402.01 cw(c1854.05,5402.01) 1854.05,5388.35 1811.49,5388.35 ccw(c1811.49,5383.69) 1806.83,5383.69 1806.83,5369.71 ccw(c1811.49,5369.71) 1811.49,5365.05 1854.05,5365.05 cw(c1854.05,5351.39) 1867.71,5351.39 1867.71,5337.41 cw(c1854.05,5337.41) 1854.05,5323.75 1811.49,5323.75 ccw(c1811.49,5319.09) 1806.83,5319.09 1806.83,5305.11 ccw(c1811.49,5305.11) 1811.49,5300.45 1854.05,5300.45 cw(c1854.05,5286.79) 1867.71,5286.79 1867.71,5272.81 cw(c1854.05,5272.81) 1854.05,5259.15 1811.49,5259.15 ccw(c1811.49,5254.49) 1806.83,5254.49 1806.83,5240.51 ccw(c1811.49,5240.51) 1811.49,5235.85 1854.05,5235.85 cw(c1854.05,5222.19) 1867.71,5222.19 1867.71,5208.21 cw(c1854.05,5208.21) 1854.05,5194.55 1811.49,5194.55 ccw(c1811.49,5189.89) 1806.83,5189.89 1806.83,5175.91 ccw(c1811.49,5175.91) 1811.49,5171.25 1854.05,5171.25 cw(c1854.05,5157.59) 1867.71,5157.59 1867.71,5143.61 cw(c1854.05,5143.61) 1854.05,5129.95 1811.49,5129.95 ccw(c1811.49,5125.29) 1806.83,5125.29 1806.83,5111.31 ccw(c1811.49,5111.31) 1811.49,5106.65 1853.41,5106.65 cw(c1853.41,5092.99) 1867.07,5092.99 1867.07,5079.01 cw(c1853.41,5079.01) 1853.41,5065.35 1818.17,5065.35 ccw(c1818.17,5060.69) 1813.51,5060.69 1813.51,5046.71 ccw(c1818.17,5046.71) 1818.17,5042.05 cw(c1818.17,5028.39) 1831.83,5028.39 1831.83,5006.17 1841.94,4996.06 1974,4864 2195.73,4864 2319,4740.73 2319,4400 2550,4169 2633,4169 2718.36,4083.64 2718.36,3973.64 2755,3937 2777.73,3937 2830,3884.73 2830,3624.27 2781,3575.27 2781,3545.45 v1@2765.08,3529.53
  other v1: 2765.08,3528.43 1511.89,5776.76
SZG_PORTC_S5_D3P: J11.10 MC3.129 | length 3775.3
  L1-TOP w3.3: v1(1511.88,5507.28) 1500.63,5518.53 1500.63,5547.62 1511.88,5558.87 J11.10@1511.88,5595.86 ; v1(2350.89,3559.55) 2351.9,3560.57 2359.78,3560.57 2366.35,3553.99 2422.03,3553.99 2437.22,3538.81 2448.79,3538.81 2454.13,3533.46 MC3.129@2476.77,3533.46
  L10-BOT w3.3: v1(1511.88,5507.28) 1495,5490.4 1495,5350.39 1495,5344.24 ccw(c1508.66,5344.24) 1508.66,5330.58 1508.98,5330.58 cw(c1508.98,5325.92) 1513.64,5325.92 1513.64,5311.94 cw(c1508.98,5311.94) 1508.98,5307.28 1483.66,5307.28 ccw(c1483.66,5293.62) 1470,5293.62 1470,5279.64 ccw(c1483.66,5279.64) 1483.66,5265.98 1508.98,5265.98 cw(c1508.98,5261.32) 1513.64,5261.32 1513.64,5247.34 cw(c1508.98,5247.34) 1508.98,5242.68 1483.66,5242.68 ccw(c1483.66,5229.02) 1470,5229.02 1470,5215.04 ccw(c1483.66,5215.04) 1483.66,5201.38 1508.98,5201.38 cw(c1508.98,5196.72) 1513.64,5196.72 1513.64,5182.74 cw(c1508.98,5182.74) 1508.98,5178.08 1483.66,5178.08 ccw(c1483.66,5164.42) 1470,5164.42 1470,5150.44 ccw(c1483.66,5150.44) 1483.66,5136.78 1508.98,5136.78 cw(c1508.98,5132.12) 1513.64,5132.12 1513.64,5118.14 cw(c1508.98,5118.14) 1508.98,5113.48 1483.66,5113.48 ccw(c1483.66,5099.82) 1470,5099.82 1470,5085.84 ccw(c1483.66,5085.84) 1483.66,5072.18 1508.98,5072.18 cw(c1508.98,5067.52) 1513.64,5067.52 1513.64,5053.54 cw(c1508.98,5053.54) 1508.98,5048.88 1483.66,5048.88 ccw(c1483.66,5035.22) 1470,5035.22 1470,5021.24 ccw(c1483.66,5021.24) 1483.66,5007.58 1508.98,5007.58 cw(c1508.98,5002.92) 1513.64,5002.92 1513.64,4988.94 cw(c1508.98,4988.94) 1508.98,4984.28 1491.81,4984.28 ccw(c1491.81,4970.62) 1478.15,4970.62 1478.15,4956.64 ccw(c1491.81,4956.64) 1491.81,4942.98 1508.66,4942.98 cw(c1508.66,4938.32) 1513.32,4938.32 1513.32,4924.34 cw(c1508.66,4924.34) 1508.66,4919.68 ccw(c1508.66,4906.02) 1495,4906.02 1495,4858.27 1495,4804.21 1503.94,4795.28 1506.97,4792.25 1529.03,4770.18 ; 1529.05,4770.17 cw(c1525.77,4766.86) 1529.06,4763.56 1523.02,4757.52 1523.02,4757.31 ccw(c1534,4749.18) 1524.36,4739.49 1534.19,4729.66 ccw(c1543.88,4739.29) 1553.54,4729.63 1575.92,4752.01 ; 1575.94,4752.03 cw(c1579.24,4748.74) 1582.53,4752.03 1592.42,4742.15 cw(c1589.12,4738.85) 1592.42,4735.56 1568.7,4711.84 1568.7,4711.63 ccw(c1579.68,4703.5) 1570.04,4693.81 1579.87,4683.98 ccw(c1589.56,4693.61) 1599.22,4683.95 1621.6,4706.33 cw(c1624.92,4703.06) 1628.21,4706.36 1638.1,4696.47 cw(c1634.8,4693.18) 1638.1,4689.88 1614.38,4666.16 1614.38,4665.95 ccw(c1625.36,4657.82) 1615.72,4648.13 1625.55,4638.3 ccw(c1635.24,4647.93) 1644.9,4638.28 1667.28,4660.65 ; 1667.3,4660.68 cw(c1670.6,4657.38) 1673.89,4660.68 1683.78,4650.79 cw(c1680.48,4647.5) 1683.78,4644.2 1660.06,4620.48 1660.06,4620.27 ccw(c1671.03,4612.14) 1661.4,4602.46 1671.23,4592.63 ccw(c1680.92,4602.26) 1690.58,4592.6 1712.96,4614.98 ; 1712.98,4615 cw(c1716.27,4611.7) 1719.57,4615 1729.46,4605.11 cw(c1726.16,4601.82) 1729.46,4598.52 1705.74,4574.8 1705.74,4574.59 ccw(c1716.71,4566.46) 1707.08,4556.78 1716.91,4546.95 ccw(c1726.6,4556.58) 1736.26,4546.92 1758.64,4569.3 ; 1758.66,4569.32 cw(c1761.95,4566.02) 1765.25,4569.32 1775.13,4559.43 cw(c1771.84,4556.14) 1775.13,4552.84 1751.41,4529.12 1751.41,4528.91 ccw(c1762.39,4520.78) 1752.76,4511.1 1762.59,4501.27 ; 1762.59,4501.27 ccw(c1772.28,4510.9) 1781.94,4501.24 1804.31,4523.62 ; 1798.44,4465.42 1808.27,4455.59 ccw(c1817.96,4465.22) 1827.62,4455.56 1849.99,4477.94 cw(c1853.31,4474.67) 1856.61,4477.96 1866.49,4468.08 cw(c1863.2,4464.78) 1866.49,4461.49 1842.77,4437.77 1842.77,4437.56 ccw(c1853.75,4429.43) 1844.12,4419.74 1853.95,4409.91 ccw(c1863.64,4419.54) 1873.29,4409.88 1895.67,4432.26 ; 1798.44,4465.42 cw(c1808.07,4475.1) 1797.09,4483.23 1797.09,4483.45 1820.81,4507.16 ccw(c1817.52,4510.46) 1820.81,4513.75 1810.93,4523.64 ccw(c1807.63,4520.34) 1804.34,4523.64 ; 1895.7,4432.28 cw(c1898.99,4428.99) 1902.29,4432.28 1912.17,4422.4 cw(c1908.88,4419.1) 1912.17,4415.81 1888.45,4392.09 1888.45,4391.88 ccw(c1899.43,4383.75) 1889.8,4374.06 1899.63,4364.23 ; 1899.63,4364.23 ccw(c1909.31,4373.86) 1918.97,4364.2 1941.35,4386.58 cw(c1944.67,4383.31) 1947.96,4386.6 1957.85,4376.72 cw(c1954.56,4373.42) 1957.85,4370.13 1934.13,4346.41 1934.13,4346.2 ccw(c1945.11,4338.07) 1935.48,4328.38 ; 1935.48,4328.38 1945.31,4318.55 ccw(c1954.99,4328.18) 1964.65,4318.52 1969.38,4323.25 cw(c1972.67,4319.95) 1975.98,4323.23 1977.28,4321.93 1980.32,4318.9 1984.25,4314.96 1984.25,4259.22 2143,4100.47 2143,3771.53 2334.27,3580.26 2340.08,3580.26 2349.28,3571.07 2349.28,3561.17 v1(2350.89,3559.55)
SZG_PORTC_S6_D2N: J11.11 MC3.132 | length 3726
  L1-TOP w3.3: MC3.132@2720.08,3553.15 2742.72,3553.15 2748.11,3547.76 2756.01,3547.76 2765.08,3556.83 v1@2765.08,3557.09
  L10-BOT w3.3: v1@1481.37,5776.76 1491.63,5766.5 1491.63,5745.64 1509.75,5727.52 1553.48,5727.52 1626,5655 1648,5655 1678,5625 1678,5596.27 1822.83,5451.44 1822.83,5440.46 1822.83,5434.31 ccw(c1836.49,5434.31) 1836.49,5420.65 1854.05,5420.65 cw(c1854.05,5415.99) 1858.71,5415.99 1858.71,5402.01 cw(c1854.05,5402.01) 1854.05,5397.35 1811.49,5397.35 ccw(c1811.49,5383.69) 1797.83,5383.69 1797.83,5369.71 ccw(c1811.49,5369.71) 1811.49,5356.05 1854.05,5356.05 cw(c1854.05,5351.39) 1858.71,5351.39 1858.71,5337.41 cw(c1854.05,5337.41) 1854.05,5332.75 1811.49,5332.75 ccw(c1811.49,5319.09) 1797.83,5319.09 1797.83,5305.11 ccw(c1811.49,5305.11) 1811.49,5291.45 1854.05,5291.45 cw(c1854.05,5286.79) 1858.71,5286.79 1858.71,5272.81 cw(c1854.05,5272.81) 1854.05,5268.15 1811.49,5268.15 ccw(c1811.49,5254.49) 1797.83,5254.49 1797.83,5240.51 ccw(c1811.49,5240.51) 1811.49,5226.85 1854.05,5226.85 cw(c1854.05,5222.19) 1858.71,5222.19 1858.71,5208.21 cw(c1854.05,5208.21) 1854.05,5203.55 1811.49,5203.55 ccw(c1811.49,5189.89) 1797.83,5189.89 1797.83,5175.91 ccw(c1811.49,5175.91) 1811.49,5162.25 1854.05,5162.25 cw(c1854.05,5157.59) 1858.71,5157.59 1858.71,5143.61 cw(c1854.05,5143.61) 1854.05,5138.95 1811.49,5138.95 ccw(c1811.49,5125.29) 1797.83,5125.29 1797.83,5111.31 ccw(c1811.49,5111.31) 1811.49,5097.65 1853.41,5097.65 cw(c1853.41,5092.99) 1858.07,5092.99 1858.07,5079.01 cw(c1853.41,5079.01) 1853.41,5074.35 1818.17,5074.35 ccw(c1818.17,5060.69) 1804.51,5060.69 1804.51,5046.71 ccw(c1818.17,5046.71) 1818.17,5033.05 cw(c1818.17,5028.39) 1822.83,5028.39 1822.83,5002.44 1829.21,4996.06 1970.27,4855 2192,4855 2310,4737 2310,4396.27 2546.27,4160 2629.27,4160 2709.36,4079.91 2709.36,3969.91 2751.27,3928 2774,3928 2821,3881 2821,3875.71 2821,3850.76 cw(c2816.34,3850.76) 2816.34,3846.1 2805.14,3846.1 ccw(c2805.14,3841.44) 2800.48,3841.44 2800.48,3827.46 ccw(c2805.14,3827.46) 2805.14,3822.8 2816.34,3822.8 cw(c2816.34,3818.14) 2821,3818.14 2821,3795.28 2821,3628 2772,3579 2772,3564.01 v1@2765.08,3557.09
  other v1: 2765.08,3558.09 1480.37,5776.76
SZG_PORTC_S7_D3N: J11.12 MC3.131 | length 3775
  L1-TOP w3.3: J11.12@1480.38,5595.86 1480.38,5559 1491.63,5547.75 1491.63,5498 v1@1511.88,5477.75 ; v1(2367.15,3575.82) 2366.14,3574.8 2366.14,3566.93 2370.08,3562.99 2425.76,3562.99 2440.94,3547.81 2448.79,3547.81 2454.13,3553.15 MC3.131@2476.77,3553.15
  L10-BOT w3.3: v1@1511.88,5477.75 1504,5469.87 1504,5440.94 1504,5418.98 ccw(c1508.66,5418.98) 1508.66,5414.32 1510.65,5414.32 cw(c1510.65,5409.66) 1515.31,5409.66 1515.31,5395.68 cw(c1510.65,5395.68) 1510.65,5391.02 1508.66,5391.02 ccw(c1508.66,5386.36) 1504,5386.36 1504,5361.41 1504,5350.39 1504,5344.24 ccw(c1508.66,5344.24) 1508.66,5339.58 1508.98,5339.58 cw(c1508.98,5325.92) 1522.64,5325.92 1522.64,5311.94 cw(c1508.98,5311.94) 1508.98,5298.28 1483.66,5298.28 ccw(c1483.66,5293.62) 1479,5293.62 1479,5279.64 ccw(c1483.66,5279.64) 1483.66,5274.98 1508.98,5274.98 cw(c1508.98,5261.32) 1522.64,5261.32 1522.64,5247.34 cw(c1508.98,5247.34) 1508.98,5233.68 1483.66,5233.68 ccw(c1483.66,5229.02) 1479,5229.02 1479,5215.04 ccw(c1483.66,5215.04) 1483.66,5210.38 1508.98,5210.38 cw(c1508.98,5196.72) 1522.64,5196.72 1522.64,5182.74 cw(c1508.98,5182.74) 1508.98,5169.08 1483.66,5169.08 ccw(c1483.66,5164.42) 1479,5164.42 1479,5150.44 ccw(c1483.66,5150.44) 1483.66,5145.78 1508.98,5145.78 cw(c1508.98,5132.12) 1522.64,5132.12 1522.64,5118.14 cw(c1508.98,5118.14) 1508.98,5104.48 1483.66,5104.48 ccw(c1483.66,5099.82) 1479,5099.82 1479,5085.84 ccw(c1483.66,5085.84) 1483.66,5081.18 1508.98,5081.18 cw(c1508.98,5067.52) 1522.64,5067.52 1522.64,5053.54 cw(c1508.98,5053.54) 1508.98,5039.88 1483.66,5039.88 ccw(c1483.66,5035.22) 1479,5035.22 1479,5021.24 ccw(c1483.66,5021.24) 1483.66,5016.58 1508.98,5016.58 cw(c1508.98,5002.92) 1522.64,5002.92 1522.64,4988.94 cw(c1508.98,4988.94) 1508.98,4975.28 1491.81,4975.28 ccw(c1491.81,4970.62) 1487.15,4970.62 1487.15,4956.64 ccw(c1491.81,4956.64) 1491.81,4951.98 1508.66,4951.98 cw(c1508.66,4938.32) 1522.32,4938.32 1522.32,4924.34 cw(c1508.66,4924.34) 1508.66,4910.68 ccw(c1508.66,4906.02) 1504,4906.02 1504,4858.27 1504,4807.94 1510.3,4801.64 1513.33,4798.61 1535.43,4776.51 ; 1535.44,4776.5 1536.74,4775.2 1536.74,4774.99 cw(c1525.77,4766.86) 1535.43,4757.2 1530.72,4752.5 ccw(c1534,4749.18) 1530.7,4745.88 1540.59,4736 ccw(c1543.88,4739.29) 1547.18,4736 1570.9,4759.72 1571.11,4759.72 cw(c1579.24,4748.74) 1588.9,4758.4 1598.78,4748.51 cw(c1589.12,4738.85) 1598.82,4729.23 1576.4,4706.82 ccw(c1579.68,4703.5) 1576.38,4700.2 1586.27,4690.32 ccw(c1589.56,4693.61) 1592.86,4690.32 1616.58,4714.04 1616.79,4714.04 cw(c1624.92,4703.06) 1634.58,4712.72 1644.46,4702.83 cw(c1634.8,4693.18) 1644.49,4683.55 1622.08,4661.14 ; 1622.06,4661.11 ccw(c1625.36,4657.82) 1622.06,4654.53 1631.95,4644.64 ccw(c1635.24,4647.93) 1638.54,4644.64 1662.26,4668.36 1662.47,4668.36 cw(c1670.6,4657.38) 1680.25,4667.04 1690.14,4657.16 cw(c1680.48,4647.5) 1690.17,4637.87 1667.76,4615.46 ccw(c1671.03,4612.14) 1667.74,4608.85 1677.62,4598.96 ccw(c1680.92,4602.26) 1684.21,4598.96 1707.93,4622.68 1708.14,4622.68 cw(c1716.27,4611.7) 1725.93,4621.36 1735.82,4611.48 cw(c1726.16,4601.82) 1735.85,4592.19 1713.44,4569.78 ; 1713.42,4569.76 ccw(c1716.71,4566.46) 1713.42,4563.17 1723.3,4553.28 ccw(c1726.6,4556.58) 1729.89,4553.28 1753.61,4577 1753.82,4577 cw(c1761.95,4566.02) 1771.61,4575.68 1781.5,4565.8 cw(c1771.84,4556.14) 1781.53,4546.51 1759.12,4524.1 ccw(c1762.39,4520.78) 1759.1,4517.49 1768.98,4507.6 ccw(c1772.28,4510.9) 1775.57,4507.6 1799.29,4531.32 1799.5,4531.32 cw(c1807.63,4520.34) 1817.29,4530 1827.18,4520.12 cw(c1817.52,4510.46) 1827.21,4500.83 1804.8,4478.42 ; 1804.78,4478.4 ccw(c1808.07,4475.1) 1804.78,4471.81 1814.66,4461.92 ccw(c1817.96,4465.22) 1821.25,4461.92 1844.97,4485.64 1845.18,4485.64 cw(c1853.31,4474.67) 1862.97,4484.33 1872.86,4474.44 cw(c1863.2,4464.78) 1872.89,4455.16 1850.48,4432.74 ; 1850.45,4432.72 ccw(c1853.75,4429.43) 1850.45,4426.13 1860.34,4416.24 ccw(c1863.64,4419.54) 1866.93,4416.24 1890.65,4439.96 1890.86,4439.96 cw(c1898.99,4428.99) 1908.65,4438.65 1918.53,4428.76 cw(c1908.88,4419.1) 1918.57,4409.48 1896.16,4387.06 ccw(c1899.43,4383.75) 1896.13,4380.45 1906.02,4370.57 ccw(c1909.31,4373.86) 1912.61,4370.57 1936.33,4394.29 1936.54,4394.29 cw(c1944.67,4383.31) 1954.33,4392.97 1964.21,4383.08 cw(c1954.56,4373.42) 1964.25,4363.8 1941.84,4341.39 ; 1941.81,4341.36 ccw(c1945.11,4338.07) 1941.81,4334.77 1951.7,4324.89 ccw(c1954.99,4328.18) 1958.29,4324.89 1963.01,4329.61 cw(c1972.67,4319.95) 1980.8,4330.93 1981.01,4330.93 1982.32,4329.62 ; 1982.33,4329.61 1983.65,4328.29 1986.68,4325.26 1993.25,4318.69 1993.25,4262.94 2152,4104.2 2152,3775.26 2338,3589.26 2343.81,3589.26 2355.64,3577.43 2365.54,3577.43 v1(2367.15,3575.82)
  other v1: 1511.88,5476.75
SZG_PORTC_S8_D4P: J11.13 MC3.122 | length 3724.5
  L1-TOP w3.3: MC3.122@2720.08,3454.72 2742.72,3454.72 2748.01,3460.02 2756.01,3460.02 2765.08,3450.95 v1@2765.08,3450.79
  L10-BOT w3.3: v1@1447.89,5866.17 1437.63,5855.9 1437.63,5791 1448,5780.63 1448,5670 1517,5601 1574.73,5601 1754.4,5421.33 1757.03,5418.7 1757.03,4948.61 1764.52,4941.12 1767.55,4938.09 1796.08,4909.57 cw(c1786.42,4899.91) 1796.08,4890.25 ccw(c1799.37,4886.95) 1796.07,4883.66 1805.96,4873.77 ccw(c1809.26,4877.07) 1812.55,4873.77 1827.58,4888.8 cw(c1837.24,4879.15) 1846.9,4888.8 1856.79,4878.92 cw(c1847.13,4869.26) 1856.82,4859.63 1837.05,4839.87 ; 1837.03,4839.85 ccw(c1840.33,4836.55) 1837.03,4833.26 1846.92,4823.37 ccw(c1850.21,4826.67) 1853.51,4823.37 1877.23,4847.09 1877.44,4847.09 cw(c1885.57,4836.11) 1895.23,4845.77 1905.11,4835.89 cw(c1895.45,4826.23) 1905.14,4816.6 1882.73,4794.19 ; 1882.71,4794.17 ccw(c1886,4790.87) 1882.71,4787.58 1892.59,4777.69 ccw(c1895.89,4780.99) 1899.18,4777.69 1922.9,4801.41 1923.12,4801.41 cw(c1931.25,4790.43) 1940.9,4800.09 1950.79,4790.21 cw(c1941.13,4780.55) 1950.82,4770.92 1928.41,4748.51 ccw(c1931.68,4745.19) 1928.39,4741.9 1938.27,4732.01 ccw(c1941.57,4735.31) 1944.86,4732.01 1968.58,4755.73 1968.79,4755.73 cw(c1976.92,4744.75) 1986.58,4754.41 1996.47,4744.53 cw(c1986.81,4734.87) 1996.5,4725.24 1974.09,4702.83 ; 1974.07,4702.81 ccw(c1977.36,4699.51) 1974.07,4696.22 1983.95,4686.33 ccw(c1987.25,4689.63) 1990.54,4686.33 2014.26,4710.05 2014.47,4710.05 cw(c2022.6,4699.08) 2032.26,4708.73 2042.15,4698.85 cw(c2032.49,4689.19) 2042.18,4679.56 2019.77,4657.15 ccw(c2023.04,4653.83) 2019.75,4650.54 2029.63,4640.65 ccw(c2032.93,4643.95) 2036.22,4640.65 2059.94,4664.37 2060.15,4664.37 cw(c2068.28,4653.4) 2077.94,4663.06 2087.83,4653.17 cw(c2078.17,4643.51) 2087.86,4633.89 2065.45,4611.47 ; 2065.43,4611.45 ccw(c2068.72,4608.16) 2065.43,4604.86 2075.31,4594.98 ccw(c2078.61,4598.27) 2081.9,4594.98 2105.62,4618.69 2105.83,4618.69 cw(c2113.96,4607.72) 2123.62,4617.38 2133.51,4607.49 cw(c2123.85,4597.83) 2133.54,4588.21 2111.13,4565.79 ccw(c2114.4,4562.48) 2111.1,4559.18 2120.99,4549.3 ccw(c2124.28,4552.59) 2127.58,4549.3 2132.3,4554.02 cw(c2141.96,4544.36) 2150.09,4555.34 2150.3,4555.34 2151.61,4554.03 2152.94,4552.7 2155.97,4549.67 2178.29,4527.35 2178.29,4337.46 2298,4217.75 2298,3978 2375,3901 2434.73,3901 2726.23,3609.5 2726.23,3566.18 2726.23,3528.77 2746,3509 2772.73,3509 2784,3497.73 2784,3469.71 v1@2765.08,3450.79
  other v1: 2765.08,3449.69 1448.89,5866.17
SZG_PORTC_S9_D5P: J11.14 MC3.125 | length 3773.6
  L1-TOP w3.3: v1(1448.88,5507.28) 1437.63,5518.53 1437.63,5547.62 1448.88,5558.87 J11.14@1448.88,5595.86 ; MC3.125@2476.77,3494.09 2499.41,3494.09 2504.7,3499.39 2512.7,3499.39 2521.77,3490.32 v1@2521.77,3490.16
  L10-BOT w3.3: v1(1448.88,5507.28) 1432,5490.4 1432,5354.33 1432,5312.98 cw(c1427.34,5312.98) 1427.34,5308.32 1420.66,5308.32 ccw(c1420.66,5294.66) 1407,5294.66 1407,5280.68 ccw(c1420.66,5280.68) 1420.66,5267.02 1428.27,5267.02 cw(c1428.27,5262.36) 1432.93,5262.36 1432.93,5248.38 cw(c1428.27,5248.38) 1428.27,5243.72 1420.66,5243.72 ccw(c1420.66,5230.06) 1407,5230.06 1407,5216.08 ccw(c1420.66,5216.08) 1420.66,5202.42 1428.27,5202.42 cw(c1428.27,5197.76) 1432.93,5197.76 1432.93,5183.78 cw(c1428.27,5183.78) 1428.27,5179.12 1420.66,5179.12 ccw(c1420.66,5165.46) 1407,5165.46 1407,5151.48 ccw(c1420.66,5151.48) 1420.66,5137.82 1428.27,5137.82 cw(c1428.27,5133.16) 1432.93,5133.16 1432.93,5119.18 cw(c1428.27,5119.18) 1428.27,5114.52 1420.66,5114.52 ccw(c1420.66,5100.86) 1407,5100.86 1407,5086.88 ccw(c1420.66,5086.88) 1420.66,5073.22 1428.27,5073.22 cw(c1428.27,5068.56) 1432.93,5068.56 1432.93,5054.58 cw(c1428.27,5054.58) 1428.27,5049.92 1420.66,5049.92 ccw(c1420.66,5036.26) 1407,5036.26 1407,5022.28 ccw(c1420.66,5022.28) 1420.66,5008.62 1428.27,5008.62 cw(c1428.27,5003.96) 1432.93,5003.96 1432.93,4989.98 cw(c1428.27,4989.98) 1428.27,4985.32 1420.66,4985.32 ccw(c1420.66,4971.66) 1407,4971.66 1407,4957.68 ccw(c1420.66,4957.68) 1420.66,4944.02 1428.27,4944.02 cw(c1428.27,4939.36) 1432.93,4939.36 1432.93,4925.38 cw(c1428.27,4925.38) 1428.27,4920.72 1420.66,4920.72 ccw(c1420.66,4907.06) 1407,4907.06 1407,4893.08 ccw(c1420.66,4893.08) 1420.66,4879.42 1428.27,4879.42 cw(c1428.27,4874.76) 1432.93,4874.76 1432.93,4860.78 cw(c1428.27,4860.78) 1428.27,4856.12 1420.66,4856.12 ccw(c1420.66,4842.46) 1407,4842.46 1407,4828.48 ccw(c1420.66,4828.48) 1420.66,4814.82 1428.27,4814.82 cw(c1428.27,4810.16) 1432.93,4810.16 1432.93,4796.18 cw(c1428.27,4796.18) 1428.27,4791.52 1420.66,4791.52 ccw(c1420.66,4777.86) 1407,4777.86 1407,4763.88 ccw(c1420.66,4763.88) 1420.66,4750.22 1427.34,4750.22 cw(c1427.34,4745.56) 1432,4745.56 1432,4739.41 1432,4732.44 1440.95,4723.48 1443.98,4720.45 1452.37,4712.06 ccw(c1462.06,4721.69) 1471.72,4712.03 cw(c1475.02,4708.74) 1478.31,4712.04 1488.2,4702.15 cw(c1484.9,4698.86) 1488.2,4695.56 1476.84,4684.21 ccw(c1486.5,4674.55) 1476.87,4664.86 1486.7,4655.03 ccw(c1496.39,4664.66) 1506.05,4655 1522.1,4671.06 ; 1522.12,4671.08 cw(c1525.42,4667.78) 1528.71,4671.08 1538.6,4661.19 cw(c1535.3,4657.9) 1538.6,4654.6 1514.88,4630.88 1514.88,4630.67 ccw(c1525.86,4622.54) 1516.22,4612.86 1526.05,4603.03 ccw(c1535.74,4612.66) 1545.4,4603 1567.78,4625.38 cw(c1571.1,4622.11) 1574.39,4625.4 1584.28,4615.52 cw(c1580.98,4612.22) 1584.28,4608.93 1560.56,4585.21 1560.56,4584.99 ccw(c1571.54,4576.86) 1561.9,4567.18 1571.73,4557.35 ccw(c1581.42,4566.98) 1591.08,4557.32 1613.46,4579.7 ; 1613.48,4579.72 cw(c1616.78,4576.43) 1620.07,4579.72 1629.96,4569.84 cw(c1626.66,4566.54) 1629.96,4563.25 1606.24,4539.53 1606.24,4539.32 ccw(c1617.21,4531.19) 1607.58,4521.5 1617.41,4511.67 ccw(c1627.1,4521.3) 1636.76,4511.64 1659.14,4534.02 cw(c1662.46,4530.75) 1665.75,4534.04 1675.64,4524.16 cw(c1672.34,4520.86) 1675.64,4517.57 1651.92,4493.85 1651.92,4493.64 ccw(c1662.89,4485.51) 1653.26,4475.82 1663.09,4465.99 ccw(c1672.78,4475.62) 1682.44,4465.96 1704.82,4488.34 ; 1704.84,4488.36 cw(c1708.13,4485.07) 1711.43,4488.36 1721.31,4478.48 cw(c1718.02,4475.18) 1721.31,4471.89 1697.6,4448.17 1697.6,4447.96 ccw(c1708.57,4439.83) 1698.94,4430.14 1708.77,4420.31 ccw(c1718.46,4429.94) 1728.12,4420.28 1750.5,4442.66 ; 1750.52,4442.68 cw(c1753.81,4439.39) 1757.11,4442.69 1766.99,4432.8 cw(c1763.7,4429.5) 1766.99,4426.21 1743.27,4402.49 1743.27,4402.28 ccw(c1754.25,4394.15) 1744.62,4384.46 1754.45,4374.63 ccw(c1764.14,4384.26) 1773.8,4374.6 1796.17,4396.98 ; 1796.2,4397.01 cw(c1799.49,4393.71) 1802.79,4397.01 1812.67,4387.12 cw(c1809.38,4383.83) 1812.67,4380.53 1788.95,4356.81 1788.95,4356.6 ccw(c1799.93,4348.47) 1790.3,4338.79 1800.13,4328.95 ccw(c1809.82,4338.58) 1819.47,4328.93 1841.85,4351.3 ; 1835.98,4293.11 cw(c1845.61,4302.79) 1834.63,4310.92 1834.63,4311.13 1858.35,4334.85 ccw(c1855.06,4338.15) 1858.35,4341.44 1848.47,4351.33 ccw(c1845.17,4348.03) 1841.88,4351.33 ; 1835.98,4293.1 1845.81,4283.28 ccw(c1855.49,4292.91) 1865.15,4283.25 1869.88,4287.97 cw(c1873.17,4284.68) 1876.48,4287.95 1877.79,4286.65 1880.82,4283.62 2101,4063.44 2101,3758.31 2356.35,3502.96 2383.34,3502.96 2403.26,3522.87 2455.09,3522.87 2478.52,3499.44 2512.49,3499.44 v1@2521.77,3490.16
  other v1: 2521.77,3489.06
